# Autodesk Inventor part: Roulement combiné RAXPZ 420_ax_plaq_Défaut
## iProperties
Shininess: 64.0
Length Units: 11269
Angle Units: 11279
Time Units: 11290
Mass Units: 11283
Length Display Precision: 3
Angle Display Precision: 2
Compacted: True
Part Number: Roulement combiné RAXPZ 420_ax_plaq_Défaut
Document SubType Name: Modeling
Created: 2006-01
Material: Par défaut
Designer: riri
Density: 0.0
Volumn: 0.0
Area: 0.0
PropertySet Name: Model Information
Control State: 0
Master: False
Checked Out: False
Author: riri
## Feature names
1. Base1
